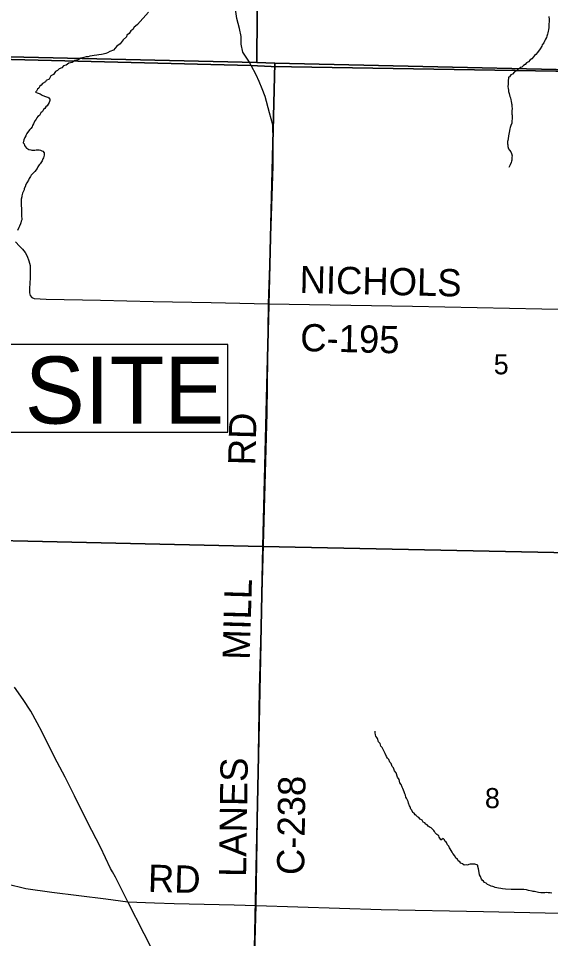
# Model space of a CAD drawing. Extents: x 0 to 34, y 0 to 22.
# Drawn here: x 6.504 to 7.614, y 15.821 to 17.741 of the extents above; entities that cross this region are included whole.
import ezdxf

# ---------------------------------------------------------------- set-up
doc = ezdxf.new("R2010")
doc.units = 0
for name, color, linetype in [('Default', 7, 'Continuous'), ('GM_X_County_Road', 7, 'Continuous'), ('GM_X_County_Road_Text', 7, 'Continuous'), ('GM_X_Minor_River', 7, 'Continuous'), ('GM_X_Section', 7, 'Continuous'), ('GM_X_Section_Text', 7, 'Continuous'), ('GM_X_Township_Road', 7, 'Continuous'), ('GM_X_US_Route', 7, 'Continuous'), ('SH_Text', 7, 'Continuous')]:
    doc.layers.add(name, color=color, linetype=linetype)

msp = doc.modelspace()

# ---------------------------------------------------------------- linework, layer by layer
at = {"layer": 'Default'}
for points in [[(8.9, 17.6104), (8.9, 20.9), (6.0871, 20.9), (6.0839, 20.7194), (6.0809, 20.5156), (6.08, 20.4768), (6.0777, 20.3704), (6.0696, 20.0002), (6.0632, 19.7108), (6.0568, 19.5343), (5.9893, 17.6676), (6.9889, 17.643), (7.0308, 17.6406), (8.0065, 17.6245)], [(5.898, 14.1), (8.9, 14.1), (8.9, 17.6104), (8.0065, 17.6245), (7.0308, 17.6406), (6.9889, 17.643), (5.9893, 17.6676), (5.9888, 17.6433), (5.9796, 17.2537), (5.9756, 17.0812), (5.9658, 16.6637), (5.9579, 16.0817), (5.9546, 15.9939), (5.9496, 15.8622), (5.9475, 15.8049), (5.945, 15.7379), (5.9423, 15.6675), (5.9419, 15.65), (5.9251, 14.9951), (5.9162, 14.6505)]]:
    msp.add_lwpolyline(points, close=True, dxfattribs=at)
at = {"layer": 'GM_X_County_Road'}
for points in [[(6.9873, 17.6467), (6.9869, 17.6478), (6.9722, 17.6709), (6.9685, 17.6871), (6.9686, 17.7032), (6.9651, 17.7202), (6.9596, 17.7407), (6.9558, 17.765)], [(7.0254, 17.1457), (7.0288, 17.2454), (7.0354, 17.4326), (7.035, 17.4864), (7.0343, 17.5188), (7.0279, 17.5438), (7.0186, 17.5782), (7.0124, 17.5943), (7.0063, 17.6096), (6.9999, 17.6235), (6.9891, 17.6425), (6.9873, 17.6467)], [(6.9899, 15.456), (6.9901, 15.4871), (6.9904, 15.5157), (6.9912, 15.5373), (6.9922, 15.6175), (6.9998, 15.8902), (7.0067, 16.3405), (7.0224, 16.9184), (7.0254, 17.1457)], [(7.0254, 17.1457), (7.3255, 17.1409), (8.0006, 17.1268), (8.0462, 17.1251), (8.0661, 17.1246), (8.0859, 17.1239), (8.1006, 17.1251), (8.1276, 17.1304), (8.1363, 17.1318), (8.1541, 17.1318), (8.1939, 17.129), (8.2324, 17.1263), (8.2628, 17.1193), (8.312, 17.1178), (8.4, 17.1155), (8.4569, 17.1141), (8.5703, 17.1117), (8.6307, 17.1102), (8.6767, 17.1096), (8.7121, 17.1081), (8.8119, 17.1058), (8.8808, 17.1047), (8.9, 17.1042)], [(5.9581, 16.0811), (6.0552, 16.0559), (6.167, 16.0244), (6.2495, 16.0005), (6.4026, 15.9558), (6.4395, 15.9448), (6.5195, 15.9258), (6.5736, 15.918), (6.6861, 15.9042), (6.7323, 15.8976)], [(6.7323, 15.8976), (6.7874, 15.896), (6.8287, 15.8947), (6.9536, 15.8914), (6.9998, 15.8902), (7.2608, 15.882), (7.474, 15.8776), (7.7629, 15.8716), (7.9749, 15.8672), (8.2725, 15.8609), (8.656, 15.8552), (8.9, 15.8485)]]:
    msp.add_lwpolyline(points, dxfattribs=at)
at = {"layer": 'GM_X_Minor_River'}
for points in [[(6.7755, 17.754), (6.7521, 17.7285), (6.7482, 17.7248), (6.7452, 17.723), (6.7424, 17.7177), (6.7385, 17.7151), (6.7349, 17.7092), (6.7303, 17.7059), (6.7291, 17.7028), (6.7221, 17.6966), (6.7162, 17.6876), (6.7089, 17.6832), (6.7022, 17.6746), (6.6945, 17.6718), (6.6899, 17.6689), (6.6861, 17.6678), (6.6834, 17.6668), (6.6803, 17.6664), (6.6773, 17.6654), (6.6719, 17.6651), (6.6673, 17.6641), (6.6616, 17.6635), (6.6574, 17.6628), (6.6529, 17.6622), (6.6494, 17.6611), (6.6448, 17.6605), (6.6402, 17.6591), (6.6337, 17.6577), (6.6283, 17.6548), (6.6215, 17.6531), (6.6157, 17.6491), (6.6088, 17.6473), (6.6037, 17.6437), (6.598, 17.6419), (6.5941, 17.6382), (6.5887, 17.6361), (6.5856, 17.6323), (6.5814, 17.6302), (6.577, 17.6238), (6.5716, 17.6209), (6.5677, 17.6145), (6.5619, 17.6116), (6.5603, 17.609), (6.5542, 17.605), (6.551, 17.6017), (6.5487, 17.5998), (6.5463, 17.5957), (6.5436, 17.5935), (6.5416, 17.5894), (6.5397, 17.5871), (6.5431, 17.5855), (6.5453, 17.5851), (6.5491, 17.5835), (6.5532, 17.5811), (6.5581, 17.5787), (6.5627, 17.5774), (6.5653, 17.5766), (6.5675, 17.575), (6.5694, 17.5727), (6.5693, 17.5697), (6.5677, 17.5655), (6.5641, 17.5584), (6.561, 17.5562), (6.559, 17.5528), (6.5563, 17.551), (6.5543, 17.5465), (6.5508, 17.5439), (6.5481, 17.5387), (6.5446, 17.5365), (6.5422, 17.5335), (6.5407, 17.5305), (6.5387, 17.5279), (6.5363, 17.5234), (6.5351, 17.5208), (6.5335, 17.5178), (6.5323, 17.5151), (6.5299, 17.511), (6.5276, 17.5092), (6.5249, 17.5055), (6.5217, 17.5006), (6.5197, 17.4984), (6.5193, 17.4957), (6.517, 17.4927), (6.5149, 17.4875), (6.514, 17.4814), (6.5155, 17.4791), (6.5162, 17.4757), (6.5206, 17.4702), (6.5233, 17.469), (6.5259, 17.4674), (6.5297, 17.4666), (6.5319, 17.4662)], [(7.6105, 17.7448), (7.6107, 17.7388), (7.6104, 17.7251), (7.6099, 17.7217), (7.6094, 17.7171), (7.609, 17.7141), (7.6082, 17.7111), (7.6077, 17.7084), (7.6061, 17.7039), (7.6053, 17.7009), (7.6033, 17.6975), (7.6021, 17.6949), (7.5997, 17.69), (7.5962, 17.6859), (7.5957, 17.6829), (7.5922, 17.6773), (7.5867, 17.6698), (7.5831, 17.6654), (7.5804, 17.6635), (7.5785, 17.6609), (7.5749, 17.6565), (7.5711, 17.6543), (7.5676, 17.6502), (7.5637, 17.6484), (7.5606, 17.645), (7.5571, 17.6428), (7.5536, 17.6395), (7.5506, 17.6384), (7.5486, 17.6358), (7.5455, 17.6344), (7.5428, 17.6314), (7.5386, 17.6292), (7.5347, 17.6248), (7.5308, 17.623), (7.5284, 17.6192), (7.5261, 17.6182), (7.5256, 17.6094), (7.5254, 17.6041), (7.5249, 17.5992), (7.5252, 17.5946), (7.5259, 17.5916), (7.5262, 17.5882), (7.5273, 17.5843), (7.529, 17.5778), (7.5301, 17.5755), (7.5307, 17.5709), (7.5315, 17.5686), (7.5321, 17.5637), (7.5328, 17.5614), (7.5331, 17.5565), (7.5334, 17.5534), (7.5329, 17.5477), (7.5332, 17.5451), (7.5331, 17.5413), (7.5334, 17.539), (7.5337, 17.5329), (7.5336, 17.5306), (7.5332, 17.528), (7.5327, 17.5227), (7.531, 17.5174), (7.5298, 17.5132), (7.5286, 17.5106), (7.5273, 17.503), (7.5264, 17.4962), (7.5251, 17.4898), (7.5246, 17.4864), (7.5242, 17.4841), (7.5241, 17.4792), (7.5244, 17.4769), (7.5247, 17.4739), (7.5261, 17.4689), (7.5283, 17.4658), (7.5309, 17.4623), (7.5323, 17.4589), (7.5334, 17.4543), (7.5333, 17.4512), (7.5328, 17.4452), (7.532, 17.4429), (7.5315, 17.4406), (7.5299, 17.4354), (7.5271, 17.4301)], [(6.5319, 17.4662), (6.5354, 17.4661), (6.5384, 17.4664), (6.5407, 17.4667), (6.5434, 17.4666), (6.5472, 17.4665), (6.5498, 17.4661), (6.5528, 17.4645), (6.5551, 17.4637), (6.5573, 17.4606), (6.5575, 17.4556), (6.5563, 17.45), (6.5547, 17.4477), (6.5531, 17.4436), (6.5495, 17.4376), (6.5468, 17.4354), (6.5444, 17.4313), (6.5428, 17.4279), (6.5378, 17.4219), (6.5354, 17.4186), (6.5307, 17.4141), (6.5291, 17.4111), (6.5264, 17.407), (6.5248, 17.4033), (6.5216, 17.3977), (6.5188, 17.3932), (6.5184, 17.3909), (6.516, 17.386), (6.5156, 17.3834), (6.5139, 17.3789), (6.5124, 17.3762), (6.5111, 17.3709), (6.5107, 17.3687), (6.5098, 17.3638), (6.5097, 17.3596), (6.5095, 17.3512), (6.5101, 17.3436), (6.51, 17.341), (6.5102, 17.3341), (6.5105, 17.3292), (6.5105, 17.3269), (6.5108, 17.3242), (6.5107, 17.3208), (6.5099, 17.3182), (6.509, 17.3148), (6.5082, 17.3121), (6.5062, 17.3076), (6.5046, 17.3046), (6.5022, 17.2982)], [(7.3678, 16.0497), (7.3648, 16.0521), (7.3625, 16.0529), (7.3588, 16.0557), (7.3565, 16.0584), (7.3535, 16.0596), (7.3513, 16.0627), (7.3479, 16.0643), (7.3457, 16.0682), (7.342, 16.0701), (7.339, 16.0736), (7.336, 16.0752), (7.3338, 16.0779), (7.3312, 16.0795), (7.329, 16.0826), (7.3267, 16.0842), (7.3245, 16.0888), (7.3227, 16.0911), (7.3209, 16.0961), (7.3194, 16.0984), (7.3177, 16.1038), (7.317, 16.1069), (7.3133, 16.1142), (7.3122, 16.1165), (7.3112, 16.1207), (7.3097, 16.123), (7.3087, 16.1272), (7.3058, 16.1341), (7.304, 16.1368), (7.3022, 16.1426), (7.2996, 16.146), (7.2979, 16.1533), (7.2946, 16.1576), (7.2921, 16.1667), (7.2884, 16.171), (7.2863, 16.1772), (7.2833, 16.1803), (7.2812, 16.1864), (7.2786, 16.1891), (7.2764, 16.1949), (7.2734, 16.1976), (7.2716, 16.2014), (7.2687, 16.2072), (7.2658, 16.2126), (7.2625, 16.2195), (7.2599, 16.2223), (7.2582, 16.2284), (7.2552, 16.2315), (7.2531, 16.2384), (7.2512, 16.2407), (7.2494, 16.2438), (7.2487, 16.2461), (7.248, 16.2507), (7.2481, 16.2537)], [(7.6164, 15.9159), (7.613, 15.9164), (7.6088, 15.9169), (7.6046, 15.917), (7.6016, 15.9167), (7.5932, 15.9169), (7.5887, 15.9174), (7.5857, 15.9178), (7.5804, 15.9191), (7.5777, 15.9195), (7.5754, 15.9204), (7.5679, 15.9217), (7.5637, 15.9229), (7.5584, 15.9234), (7.5478, 15.9237), (7.5409, 15.9239), (7.5379, 15.9239), (7.5318, 15.9237), (7.5196, 15.924), (7.5136, 15.9249), (7.5098, 15.9254), (7.5049, 15.9267), (7.498, 15.928), (7.4958, 15.9288), (7.4931, 15.93), (7.4901, 15.9304), (7.486, 15.9325), (7.4826, 15.9337), (7.4792, 15.9368), (7.4758, 15.938), (7.4736, 15.9411), (7.471, 15.9427), (7.4695, 15.9454), (7.4678, 15.9504), (7.4659, 15.9542), (7.4643, 15.9634), (7.4636, 15.9664), (7.4622, 15.9718), (7.4618, 15.9741), (7.4562, 15.9761), (7.452, 15.9766), (7.4493, 15.9767), (7.4459, 15.9764), (7.4432, 15.9757), (7.4406, 15.9746), (7.4383, 15.9747), (7.4333, 15.9744), (7.4303, 15.9768), (7.427, 15.9784), (7.4244, 15.9815), (7.4214, 15.9831), (7.4195, 15.9869), (7.4165, 15.9889), (7.4144, 15.9939), (7.4103, 15.9989), (7.4085, 16.0016), (7.4041, 16.0082), (7.403, 16.0105), (7.4015, 16.0143), (7.3989, 16.0171), (7.3968, 16.0217), (7.3942, 16.024), (7.3923, 16.0275), (7.3901, 16.0298), (7.3878, 16.0284), (7.3851, 16.0265), (7.3844, 16.0288), (7.3818, 16.0327), (7.3811, 16.0354), (7.3766, 16.0385), (7.3729, 16.0416), (7.3714, 16.0443), (7.37, 16.0467), (7.3678, 16.0497)]]:
    msp.add_lwpolyline(points, dxfattribs=at)
at = {"layer": 'GM_X_Section'}
for points in [[(6.0336, 18.6715), (7.008, 18.6577), (7.0009, 17.6487), (5.9983, 17.6719)], [(7.008, 18.6577), (7.9821, 18.6451), (7.9657, 17.6264), (7.0384, 17.6474), (7.0009, 17.6487)], [(5.9983, 17.6719), (7.0009, 17.6487), (7.0384, 17.6474), (7.0136, 16.6391), (5.9708, 16.6629)], [(7.0384, 17.6474), (7.9657, 17.6264), (8.0077, 17.6258), (7.9916, 16.6192), (7.0136, 16.6391)], [(5.9708, 16.6629), (7.0136, 16.6391), (6.9929, 15.633), (5.9463, 15.655)], [(7.0136, 16.6391), (7.9916, 16.6192), (7.9729, 15.6119), (6.9929, 15.633)]]:
    msp.add_lwpolyline(points, close=True, dxfattribs=at)
at = {"layer": 'GM_X_Township_Road'}
msp.add_lwpolyline([(6.498, 17.2747), (6.5059, 17.266), (6.5121, 17.2598), (6.5179, 17.2525), (6.522, 17.2451), (6.5258, 17.2352), (6.5282, 17.2252), (6.528, 17.2), (6.527, 17.1777), (6.5272, 17.1686), (6.5283, 17.1632), (6.5315, 17.1586), (6.5369, 17.1564), (6.5618, 17.155), (6.6753, 17.1531), (6.7846, 17.1506), (6.9058, 17.148), (7.0254, 17.1457)], dxfattribs=at)
at = {"layer": 'GM_X_US_Route'}
for points in [[(6.7002, 15.9601), (6.6961, 15.9677), (6.6747, 16.0118), (6.6479, 16.0641), (6.6206, 16.1191), (6.6012, 16.1581), (6.5848, 16.189), (6.5716, 16.2153), (6.5534, 16.2521), (6.5432, 16.2712), (6.5296, 16.2954), (6.5135, 16.32), (6.4959, 16.3456)], [(6.9849, 15.4008), (6.9825, 15.4059), (6.9751, 15.4194), (6.963, 15.4425), (6.9446, 15.48), (6.9316, 15.5066), (6.9221, 15.5241), (6.9108, 15.5473), (6.8973, 15.5733), (6.8796, 15.6079), (6.8561, 15.654), (6.8335, 15.6979), (6.8148, 15.7355), (6.7921, 15.78), (6.7662, 15.8309), (6.7323, 15.8976), (6.7062, 15.9492), (6.7002, 15.9601)]]:
    msp.add_lwpolyline(points, dxfattribs=at)
at = {"layer": 'SH_Text'}
msp.add_lwpolyline([(6.9407, 17.0606), (6.4777, 17.0606), (6.4777, 16.8774), (6.9407, 16.8774)], close=True, dxfattribs=at)

# ---------------------------------------------------------------- texts
at = {"layer": 'GM_X_County_Road_Text'}
for s, rotation, p in [('NICHOLS', 358.7306, (7.0899, 17.1681)), ('C-195', 358.6227, (7.0912, 17.047)), ('RD', 88.5184, (6.9979, 16.808)), ('MILL', 88.3941, (6.9863, 16.4022)), ('LANES', 89.1481, (6.9787, 15.9494)), ('C-238', 89.1739, (7.0998, 15.9535)), ('RD', 358.5196, (6.7735, 15.9189))]:
    msp.add_text(s, height=0.05682, rotation=rotation, dxfattribs=at).set_placement(p)
at = {"layer": 'GM_X_Section_Text'}
for s, p in [('5', (7.4953, 16.9984)), ('8', (7.4769, 16.0933))]:
    msp.add_text(s, height=0.0419, rotation=0, dxfattribs=at).set_placement(p)
at = {"layer": 'SH_Text'}
msp.add_text('SITE', height=0.14, dxfattribs=at).set_placement((6.5172, 16.8956))

doc.saveas('drawing.dxf')
